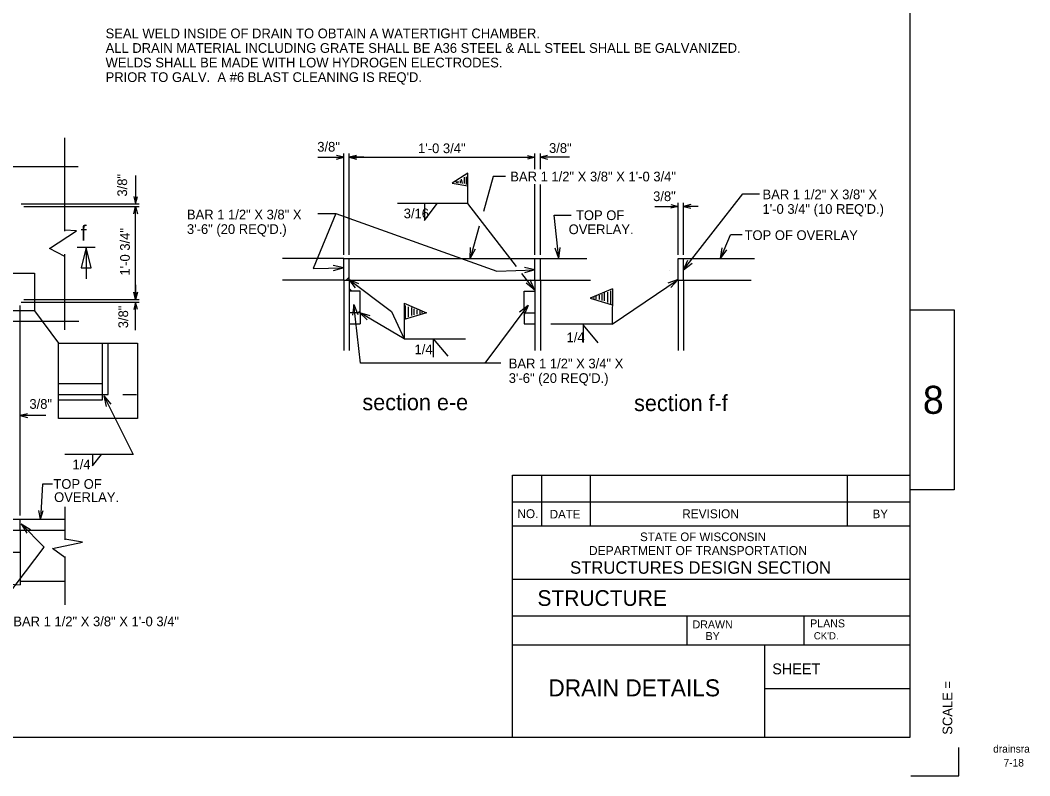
# Model space of a CAD drawing. Extents: x 973.2 to 1069.7, y 1484.4 to 1549.5.
# Drawn here: x 1034.82 to 1069.47, y 1487.1 to 1513.03 of the extents above; entities that cross this region are included whole.
import ezdxf

# ---------------------------------------------------------------- set-up
doc = ezdxf.new("R2010")
doc.units = 0
doc.layers.add('Level 1', color=7, linetype='Continuous')
doc.layers.add('Level 2', color=7, linetype='Continuous')

msp = doc.modelspace()

# ---------------------------------------------------------------- linework, layer by layer
at = {"layer": 'Level 1'}
for p, q in [((1065.368, 1488.431), (1065.368, 1544.364)), ((1051.72, 1497.42), (1065.377, 1497.42)), ((1051.72, 1495.673), (1051.72, 1497.42)), ((1052.728, 1495.673), (1052.728, 1497.42)), ((1054.392, 1495.673), (1054.392, 1497.42)), ((1063.214, 1495.673), (1063.214, 1497.42)), ((1051.72, 1496.504), (1065.377, 1496.504)), ((1051.72, 1488.431), (1051.72, 1495.673)), ((1051.72, 1495.673), (1065.377, 1495.673)), ((1051.72, 1493.842), (1065.377, 1493.842)), ((1051.72, 1492.593), (1065.377, 1492.593)), ((1057.714, 1491.595), (1057.714, 1492.593)), ((1061.727, 1491.595), (1061.727, 1492.593)), ((1051.72, 1491.595), (1065.377, 1491.595)), ((1060.375, 1488.431), (1060.375, 1491.594)), ((1060.377, 1490.096), (1065.368, 1490.096)), ((981.8, 1488.431), (1065.368, 1488.431)), ((1067.033, 1487.1), (1067.033, 1488.066)), ((1065.388, 1487.1), (1067.033, 1487.1))]:
    msp.add_line(p, q, dxfattribs=at)
msp.add_lwpolyline([(1065.368, 1503.093), (1066.88, 1503.093), (1066.88, 1496.91), (1065.368, 1496.91)], close=True, dxfattribs=at)
at = {"layer": 'Level 2'}
for p, q in [((1036.353, 1505.794), (1036.353, 1508.989)), ((1045.038, 1508.327), (1045.923, 1508.327)), ((1045.923, 1504.982), (1045.923, 1508.452)), ((1046.111, 1504.982), (1046.111, 1508.452)), ((1046.111, 1505.107), (1046.111, 1508.452)), ((1046.111, 1508.327), (1052.486, 1508.327)), ((1046.611, 1508.327), (1046.111, 1508.327)), ((1051.986, 1508.327), (1052.486, 1508.327)), ((1052.486, 1507.912), (1052.486, 1508.452)), ((1052.673, 1507.912), (1052.673, 1508.452)), ((1053.667, 1508.327), (1052.673, 1508.327)), ((1031.941, 1508.01), (1036.804, 1508.01)), ((1038.777, 1507.701), (1038.777, 1506.729)), ((1050.186, 1507.775), (1049.646, 1507.441)), ((1049.808, 1507.441), (1049.781, 1507.495)), ((1049.853, 1507.441), (1049.853, 1507.504)), ((1049.934, 1507.441), (1049.934, 1507.531)), ((1049.997, 1507.423), (1049.97, 1507.577)), ((1050.069, 1507.423), (1050.069, 1507.64)), ((1050.132, 1507.396), (1050.132, 1507.658)), ((1050.186, 1506.739), (1050.186, 1507.775)), ((1051.055, 1507.664), (1050.717, 1506.465)), ((1051.479, 1507.664), (1051.055, 1507.664)), ((1049.646, 1507.441), (1050.186, 1507.342)), ((1052.486, 1504.982), (1052.486, 1507.4)), ((1052.486, 1505.107), (1052.486, 1507.267)), ((1052.673, 1504.982), (1052.673, 1507.391)), ((1057.59, 1504.458), (1059.618, 1507.072)), ((1059.618, 1507.072), (1060.195, 1507.072)), ((1034.849, 1506.729), (1038.902, 1506.729)), ((1034.943, 1506.635), (1038.902, 1506.635)), ((1035.068, 1506.635), (1038.902, 1506.635)), ((1038.777, 1503.448), (1038.777, 1506.635)), ((1038.777, 1506.135), (1038.777, 1506.635)), ((1050.186, 1506.739), (1047.774, 1506.739)), ((1048.692, 1506.739), (1048.692, 1506.152)), ((1048.692, 1506.152), (1049.133, 1506.739)), ((1051.859, 1504.573), (1050.186, 1506.739)), ((1056.604, 1506.641), (1057.403, 1506.641)), ((1057.403, 1504.982), (1057.403, 1506.766)), ((1057.59, 1504.982), (1057.59, 1506.766)), ((1058.09, 1506.641), (1057.59, 1506.641)), ((1045.648, 1506.391), (1044.877, 1504.512)), ((1045.038, 1506.391), (1045.648, 1506.391)), ((1045.648, 1506.391), (1051.175, 1504.422)), ((1053.304, 1504.857), (1053.143, 1506.337)), ((1053.143, 1506.337), (1053.734, 1506.337)), ((1035.827, 1505.2), (1036.754, 1505.802)), ((1036.754, 1505.802), (1036.353, 1505.827)), ((1050.574, 1505.962), (1050.262, 1504.857)), ((1058.851, 1504.857), (1059.202, 1505.661)), ((1059.599, 1505.661), (1059.202, 1505.661)), ((1036.353, 1504.924), (1035.827, 1505.2)), ((1037.395, 1505.231), (1036.771, 1505.231)), ((1037.083, 1505.231), (1037.083, 1504.152)), ((1050.262, 1504.857), (1050.274, 1505.228)), ((1050.262, 1504.857), (1050.447, 1505.179)), ((1053.304, 1504.857), (1053.176, 1505.206)), ((1053.304, 1504.857), (1053.355, 1505.225)), ((1058.851, 1504.857), (1058.913, 1505.223)), ((1058.851, 1504.857), (1059.078, 1505.151)), ((1036.353, 1502.408), (1036.353, 1504.995)), ((1045.923, 1504.857), (1043.821, 1504.857)), ((1045.923, 1504.108), (1045.923, 1504.857)), ((1045.923, 1504.857), (1046.11, 1504.857)), ((1046.111, 1504.108), (1046.111, 1504.857)), ((1046.111, 1504.857), (1052.485, 1504.857)), ((1052.486, 1504.108), (1052.486, 1504.857)), ((1052.486, 1504.857), (1052.673, 1504.857)), ((1052.673, 1504.108), (1052.673, 1504.857)), ((1052.673, 1504.857), (1054.271, 1504.857)), ((1057.403, 1504.108), (1057.403, 1504.857)), ((1057.403, 1504.857), (1057.59, 1504.857)), ((1057.59, 1504.108), (1057.59, 1504.857)), ((1057.59, 1504.857), (1060.019, 1504.857)), ((1057.59, 1504.458), (1057.74, 1504.798)), ((1044.877, 1504.512), (1045.923, 1504.53)), ((1045.923, 1504.53), (1045.562, 1504.614)), ((1045.923, 1504.53), (1045.565, 1504.434)), ((1051.175, 1504.422), (1052.486, 1504.458)), ((1052.486, 1504.458), (1052.123, 1504.538)), ((1052.486, 1504.458), (1052.128, 1504.358)), ((1057.112, 1504.446), (1057.113, 1504.446)), ((1057.59, 1504.458), (1057.882, 1504.687)), ((1045.923, 1504.108), (1043.819, 1504.108)), ((1045.923, 1504.108), (1046.11, 1504.108)), ((1045.923, 1504.108), (1045.923, 1501.699)), ((1046.009, 1504.108), (1046.108, 1504.207)), ((1046.085, 1504.137), (1047.562, 1503.034)), ((1046.085, 1504.137), (1046.428, 1503.994)), ((1046.085, 1504.137), (1046.32, 1503.85)), ((1046.111, 1504.108), (1046.111, 1501.699)), ((1046.111, 1504.108), (1052.485, 1504.108)), ((1052.473, 1503.777), (1052.042, 1504.335)), ((1052.473, 1503.777), (1052.324, 1504.117)), ((1052.486, 1504.108), (1052.673, 1504.108)), ((1052.486, 1504.108), (1052.486, 1501.699)), ((1052.673, 1504.108), (1052.673, 1501.699)), ((1052.673, 1504.108), (1054.396, 1504.108)), ((1055.134, 1502.599), (1057.402, 1504.136)), ((1057.402, 1504.136), (1057.053, 1504.009)), ((1057.402, 1504.136), (1057.154, 1503.86)), ((1057.403, 1504.108), (1057.59, 1504.108)), ((1057.403, 1504.108), (1057.403, 1501.699)), ((1057.59, 1504.108), (1057.59, 1501.699)), ((1057.59, 1504.108), (1059.909, 1504.108)), ((1038.777, 1503.948), (1038.777, 1503.448)), ((1046.486, 1503.732), (1046.108, 1503.732)), ((1046.108, 1503.732), (1046.108, 1502.983)), ((1046.111, 1503.827), (1046.201, 1503.736)), ((1046.486, 1502.982), (1046.486, 1503.732)), ((1052.111, 1502.982), (1052.111, 1503.732)), ((1052.111, 1503.732), (1052.486, 1503.732)), ((1052.473, 1503.777), (1052.182, 1504.007)), ((1052.486, 1503.732), (1052.486, 1502.983)), ((1055.143, 1503.815), (1054.378, 1503.49)), ((1054.985, 1503.346), (1054.985, 1503.693)), ((1055.093, 1503.301), (1055.093, 1503.738)), ((1055.143, 1503.815), (1055.134, 1502.599)), ((1034.849, 1503.354), (1038.902, 1503.354)), ((1034.943, 1503.448), (1038.902, 1503.448)), ((1035.068, 1503.448), (1038.902, 1503.448)), ((1038.777, 1502.391), (1038.777, 1503.354)), ((1054.378, 1503.49), (1055.139, 1503.265)), ((1054.522, 1503.477), (1054.522, 1503.517)), ((1054.589, 1503.454), (1054.589, 1503.572)), ((1054.697, 1503.441), (1054.697, 1503.589)), ((1054.796, 1503.414), (1054.796, 1503.63)), ((1054.877, 1503.396), (1054.877, 1503.671)), ((1034.818, 1499.584), (1034.818, 1503.244)), ((1035.311, 1503.057), (1036.134, 1501.95)), ((1046.272, 1503.277), (1046.224, 1502.91)), ((1046.503, 1501.255), (1046.272, 1503.277)), ((1046.272, 1503.277), (1046.403, 1502.93)), ((1046.409, 1502.982), (1046.487, 1503.06)), ((1048.003, 1502.098), (1046.463, 1503.003)), ((1046.463, 1503.003), (1046.819, 1502.898)), ((1046.463, 1503.003), (1046.728, 1502.743)), ((1047.562, 1503.034), (1048.003, 1502.098)), ((1047.994, 1503.314), (1048.003, 1502.098)), ((1047.994, 1503.314), (1048.759, 1502.989)), ((1048.759, 1502.989), (1047.998, 1502.764)), ((1048.044, 1502.8), (1048.044, 1503.237)), ((1048.152, 1502.845), (1048.152, 1503.192)), ((1048.26, 1502.895), (1048.26, 1503.17)), ((1048.341, 1502.913), (1048.341, 1503.129)), ((1048.44, 1502.94), (1048.44, 1503.088)), ((1048.548, 1502.953), (1048.548, 1503.071)), ((1048.615, 1502.976), (1048.615, 1503.016)), ((1050.781, 1501.255), (1052.249, 1503.241)), ((1052.249, 1503.241), (1051.962, 1503.005)), ((1052.249, 1503.241), (1052.107, 1502.898)), ((1032.818, 1502.7), (1036.83, 1502.7)), ((1046.486, 1502.982), (1046.106, 1502.982)), ((1046.486, 1502.982), (1046.486, 1502.607)), ((1052.111, 1502.982), (1052.111, 1502.607)), ((1052.111, 1502.982), (1052.486, 1502.982)), ((1046.111, 1502.607), (1046.486, 1502.607)), ((1052.111, 1502.607), (1052.485, 1502.607)), ((1055.134, 1502.599), (1053.037, 1502.599)), ((1054.144, 1502.599), (1054.144, 1501.97)), ((1054.147, 1502.563), (1054.647, 1501.96)), ((1048.003, 1502.098), (1050.1, 1502.098)), ((1048.993, 1502.098), (1048.993, 1501.469)), ((1048.993, 1502.098), (1049.493, 1501.495)), ((1037.648, 1499.997), (1037.648, 1501.934)), ((1037.836, 1500.184), (1037.836, 1501.934)), ((1051.318, 1501.255), (1046.503, 1501.255)), ((1036.15, 1500.559), (1037.648, 1500.559)), ((1036.15, 1500.184), (1037.836, 1500.184)), ((1036.15, 1499.997), (1037.648, 1499.997)), ((1037.685, 1500.138), (1038.697, 1498.121)), ((1037.685, 1500.138), (1037.927, 1499.857)), ((1037.685, 1500.138), (1037.766, 1499.776)), ((1038.336, 1500.184), (1038.808, 1500.184)), ((1034.818, 1496.029), (1034.818, 1499.584)), ((1035.701, 1499.459), (1034.818, 1499.459)), ((1038.697, 1498.121), (1036.355, 1498.121)), ((1037.297, 1498.121), (1037.297, 1497.734)), ((1037.297, 1497.734), (1037.613, 1498.121)), ((1035.58, 1497.113), (1035.517, 1495.904)), ((1035.931, 1497.113), (1035.58, 1497.113)), ((1035.517, 1495.904), (1035.458, 1496.207)), ((1035.517, 1495.904), (1035.608, 1496.2)), ((1036.353, 1496.325), (1036.353, 1495.197)), ((1024.224, 1495.904), (1034.818, 1495.904)), ((1034.818, 1495.529), (1034.818, 1495.904)), ((1034.818, 1495.904), (1036.353, 1495.904)), ((1035.642, 1494.951), (1034.85, 1495.743)), ((1034.85, 1495.743), (1035.169, 1495.552)), ((1034.85, 1495.743), (1035.041, 1495.424)), ((1024.224, 1495.529), (1034.818, 1495.529)), ((1034.818, 1495.529), (1034.818, 1493.654)), ((1034.818, 1495.529), (1036.353, 1495.529)), ((1035.927, 1494.896), (1036.955, 1495.122)), ((1036.955, 1495.122), (1036.353, 1495.222)), ((1024.224, 1494.779), (1034.818, 1494.779)), ((1033.748, 1492.456), (1035.642, 1494.951)), ((1036.353, 1494.595), (1035.927, 1494.896)), ((1036.353, 1494.62), (1036.353, 1492.966)), ((1024.13, 1494.284), (1034.818, 1493.654)), ((1034.818, 1493.779), (1036.353, 1493.779))]:
    msp.add_line(p, q, dxfattribs=at)
for points in [[(1045.673, 1508.265), (1045.923, 1508.327), (1045.673, 1508.39)], [(1046.361, 1508.39), (1046.111, 1508.327), (1046.361, 1508.265)], [(1046.361, 1508.265), (1046.111, 1508.327), (1046.361, 1508.39)], [(1052.236, 1508.39), (1052.486, 1508.327), (1052.236, 1508.265)], [(1052.236, 1508.39), (1052.486, 1508.327), (1052.236, 1508.265)], [(1052.923, 1508.39), (1052.673, 1508.327), (1052.923, 1508.265)], [(1038.715, 1506.979), (1038.777, 1506.729), (1038.84, 1506.979)], [(1038.715, 1506.385), (1038.777, 1506.635), (1038.84, 1506.385)], [(1038.715, 1506.385), (1038.777, 1506.635), (1038.84, 1506.385)], [(1057.153, 1506.704), (1057.403, 1506.641), (1057.153, 1506.579)], [(1057.84, 1506.704), (1057.59, 1506.641), (1057.84, 1506.579)], [(1038.715, 1503.698), (1038.777, 1503.448), (1038.84, 1503.698)], [(1038.84, 1503.698), (1038.777, 1503.448), (1038.715, 1503.698)], [(1038.84, 1503.104), (1038.777, 1503.354), (1038.715, 1503.104)], [(1035.068, 1499.522), (1034.818, 1499.459), (1035.068, 1499.397)]]:
    msp.add_lwpolyline(points, dxfattribs=at)
for points in [[(1037.259, 1504.527), (1037.083, 1505.231), (1036.907, 1504.527)], [(1033.951, 1503.057), (1033.951, 1504.346), (1035.311, 1504.346), (1035.311, 1503.057)], [(1036.134, 1499.363), (1036.134, 1501.95), (1038.839, 1501.95), (1038.839, 1499.363)]]:
    msp.add_lwpolyline(points, close=True, dxfattribs=at)

# ---------------------------------------------------------------- texts
at = {"layer": 'Level 1'}
for s, height, p in [('8', 0.962, (1065.802, 1499.521)), ('NO.', 0.3034, (1051.884, 1495.943)), ('DATE', 0.2953, (1052.996, 1495.93)), ('REVISION', 0.3041, (1057.541, 1495.94)), ('BY', 0.2952, (1064.076, 1495.939)), ('STATE OF WISCONSIN', 0.295, (1056.096, 1495.153)), ('DEPARTMENT OF TRANSPORTATION', 0.3101, (1054.338, 1494.673)), ('STRUCTURES DESIGN SECTION', 0.42749, (1053.692, 1494.033)), ('STRUCTURE', 0.5387, (1052.573, 1492.931)), ('DRAWN', 0.2723, (1057.898, 1492.159)), ('PLANS', 0.2726, (1061.934, 1492.193)), ('BY', 0.2717, (1058.345, 1491.761)), ("CK'D.", 0.2469, (1062.059, 1491.781)), ('SHEET', 0.3694, (1060.633, 1490.585))]:
    msp.add_text(s, height=height, dxfattribs=at).set_placement(p)
msp.add_text('SCALE =          ', height=0.33294, rotation=90, dxfattribs=at).set_placement((1066.813, 1488.509))
at = {"layer": 'Level 2'}
for s, height, p in [('SEAL WELD INSIDE OF DRAIN TO OBTAIN A WATERTIGHT CHAMBER.', 0.33333, (1037.749, 1512.409)), ('ALL DRAIN MATERIAL INCLUDING GRATE SHALL BE A36 STEEL & ALL STEEL SHALL BE GALVANIZED.', 0.33333, (1037.749, 1511.909)), ('WELDS SHALL BE MADE WITH LOW HYDROGEN ELECTRODES.', 0.33333, (1037.749, 1511.409)), ("PRIOR TO GALV.  A #6 BLAST CLEANING IS REQ'D.", 0.33333, (1037.749, 1510.909)), ('3/8"', 0.3333, (1045.015, 1508.519)), ('1\'-0 3/4"', 0.3333, (1048.475, 1508.467)), ('3/8"', 0.3333, (1052.97, 1508.476)), ('BAR 1 1/2" X 3/8" X 1\'-0 3/4"', 0.33333, (1051.64, 1507.498)), ('3/8"', 0.3333, (1056.543, 1506.821)), ('BAR 1 1/2" X 3/8" X ', 0.33333, (1060.298, 1506.884)), ('BAR 1 1/2" X 3/8" X ', 0.33333, (1040.541, 1506.194)), ('3/16', 0.3333, (1047.982, 1506.231)), ('TOP OF', 0.3333, (1053.895, 1506.17)), ('1\'-0 3/4" (10 REQ\'D.)', 0.33333, (1060.298, 1506.384)), ('3\'-6" (20 REQ\'D.)', 0.33333, (1040.541, 1505.694)), ('OVERLAY.', 0.3333, (1053.644, 1505.687)), ('TOP OF OVERLAY', 0.33333, (1059.681, 1505.486)), ('1/4', 0.3333, (1053.572, 1501.979)), ('1/4', 0.3333, (1048.353, 1501.567)), ('BAR 1 1/2" X 3/4" X ', 0.33333, (1051.587, 1501.081)), ('3\'-6" (20 REQ\'D.)', 0.33333, (1051.587, 1500.581)), ('section e-e', 0.555, (1046.564, 1499.644)), ('3/8"', 0.3333, (1035.134, 1499.693)), ('section f-f', 0.555, (1055.889, 1499.616)), ('1/4', 0.3333, (1036.613, 1497.62)), ('TOP OF', 0.3333, (1035.958, 1496.948)), ('OVERLAY.', 0.3333, (1035.982, 1496.495)), ('BAR 1 1/2" X 3/8" X 1\'-0 3/4"', 0.33333, (1034.582, 1492.23)), ('DRAIN DETAILS', 0.58333, (1052.946, 1489.826)), ('drainsra', 0.2604, (1068.215, 1487.895)), ('7-18', 0.2604, (1068.573, 1487.418))]:
    msp.add_text(s, height=height, dxfattribs=at).set_placement(p)
for s, height, rotation, p in [('3/8"', 0.3333, 90, (1038.487, 1506.976)), ('f ', 0.5333, 360, (1036.899, 1505.458)), ('1\'-0 3/4"', 0.3333, 90, (1038.581, 1504.267)), ('3/8"', 0.3333, 90, (1038.522, 1502.457))]:
    msp.add_text(s, height=height, rotation=rotation, dxfattribs=at).set_placement(p)

doc.saveas('drawing.dxf')
